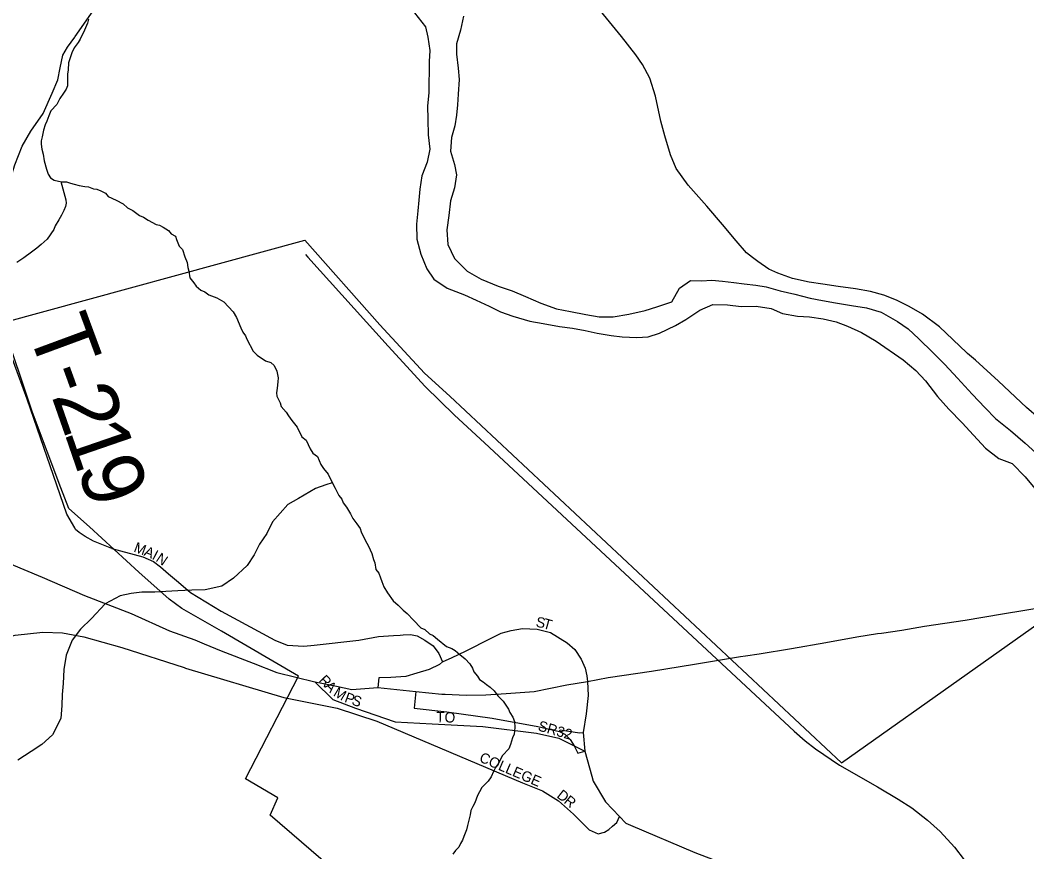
# Model space of a CAD drawing. Extents: x 1310247 to 1664935, y 235267 to 584339.
# Drawn here: x 1486473 to 1491348, y 398512 to 402543 of the extents above; entities that cross this region are included whole.
import ezdxf

# ---------------------------------------------------------------- set-up
doc = ezdxf.new("R2010")
doc.units = 0
for name, color, linetype in [('GM_X_City_Street', 7, 'Continuous'), ('GM_X_City_Street_Text', 7, 'Continuous'), ('GM_X_Corporation', 7, 'Continuous'), ('GM_X_County_Road', 7, 'Continuous'), ('GM_X_Interchange_Ramps', 7, 'Continuous'), ('GM_X_Major_River', 7, 'Continuous'), ('GM_X_Minor_River', 7, 'Continuous'), ('GM_X_Rail_Line', 7, 'Continuous'), ('GM_X_State_Route', 7, 'Continuous'), ('GM_X_Township_Road', 7, 'Continuous'), ('GM_X_Township_Road_Text', 7, 'Continuous'), ('GM_X_Township_ROW', 7, 'Continuous')]:
    doc.layers.add(name, color=color, linetype=linetype)

msp = doc.modelspace()

# ---------------------------------------------------------------- linework, layer by layer
at = {"layer": 'GM_X_City_Street'}
for points in [[(1486916.9, 399981.5), (1487066.1, 399941.7), (1487118.1, 399918.7), (1487153.1, 399893.3), (1487191.8, 399859.6), (1487240.1, 399818.2)], [(1487240.1, 399818.2), (1487298.2, 399768.5), (1487446.8, 399678.9), (1487706.8, 399537.1), (1487765.6, 399512.7), (1487846.5, 399507.8), (1487896, 399513.9), (1488112.3, 399538), (1488207.7, 399555), (1488281.4, 399559.8), (1488313.5, 399562.3)], [(1488313.5, 399562.3), (1488327.3, 399563.4), (1488362.3, 399564.7), (1488395, 399558.6), (1488432.4, 399538), (1488472.3, 399510.3), (1488500.1, 399472.8), (1488518.2, 399432.9), (1488564.1, 399453.4), (1488629.9, 399483.6), (1488753.2, 399547.7), (1488802.7, 399571.9), (1488851, 399585.2), (1488905.4, 399593.6), (1488976.6, 399591.2), (1489040.7, 399575.5), (1489121.6, 399524.8), (1489159.1, 399492.1), (1489189.2, 399446.2), (1489208.6, 399401.5), (1489217, 399364), (1489219.7, 399337.1), (1489223.9, 399270), (1489214.2, 399179.9), (1489199.6, 399090.9), (1489206.7, 399000.3), (1489241, 398878.3)], [(1487266.3, 399404.6), (1487274.1, 399402.1), (1487750.3, 399259.5), (1488007.5, 399207.3), (1488199.7, 399144.9), (1488905.1, 398847), (1489002.5, 398807.5), (1489079.4, 398758.5), (1489152.1, 398694.8), (1489228.5, 398619.2), (1489272.4, 398599.3), (1489301.7, 398607.6), (1489322.7, 398620.3), (1489341.8, 398635.6), (1489361.5, 398653.4), (1489375.4, 398682.7)], [(1487900.2, 399336), (1487987.4, 399249.9), (1488096.5, 399207.6), (1488289.2, 399141.5), (1488467.1, 399131.8), (1488712.9, 399118.7), (1488972.4, 399087.2), (1489082, 399062.9), (1489154.7, 399026.3), (1489206.7, 399000.3)], [(1489241, 398878.3), (1489247.5, 398855.1), (1489307.4, 398753.7), (1489375.4, 398682.7), (1489405.2, 398651.5), (1489428.4, 398641.7), (1489740.3, 398508.4), (1490116.4, 398364.2), (1490359.6, 398271.1), (1490717, 398147.3), (1490944.2, 398061.7), (1491029.9, 398020.8)]]:
    msp.add_lwpolyline(points, dxfattribs=at)
at = {"layer": 'GM_X_Corporation'}
msp.add_lwpolyline([(1488990.7, 397561.9), (1487683.9, 398690.3), (1487720.9, 398773.2), (1487564.1, 398864.9), (1487820, 399362.9), (1487447.5, 399580.5), (1487255.3, 399691.5), (1487194.8, 399735.7), (1487047.4, 399867.2), (1486809, 400086.1), (1486708.2, 400175.8), (1486669.7, 400275.4), (1486532.6, 400641), (1486388, 401075), (1487851.2, 401476.2), (1488214.9, 401066.4), (1488430.7, 400832.3), (1488552.7, 400719.8), (1490450.7, 398943), (1491744.2, 399861)], dxfattribs=at)
at = {"layer": 'GM_X_County_Road'}
msp.add_lwpolyline([(1485407.1, 397346.1), (1485431.1, 397452.2), (1485750.6, 398747.9), (1485799, 398922.1), (1485849.4, 399078.7), (1485913, 399202.8), (1485987.5, 399299), (1486071, 399378), (1486205.4, 399468.8), (1486324.3, 399527.5), (1486448.4, 399561.2), (1486583.4, 399576.5), (1486678.2, 399573.3), (1486780.7, 399553.6), (1486964.7, 399502.7), (1487266.3, 399404.6)], dxfattribs=at)
at = {"layer": 'GM_X_Interchange_Ramps'}
for points in [[(1488518.2, 399432.9), (1488503.1, 399419.2), (1488453.7, 399395.5), (1488393.7, 399377.2), (1488340.4, 399362.2), (1488267.1, 399357.2), (1488209.9, 399355.8), (1488204.4, 399308.4)], [(1488388.4, 399289.2), (1488380, 399208.6), (1488538.6, 399190.6), (1488758.5, 399158.9), (1488980, 399118.9), (1489083.8, 399095.1), (1489109.9, 399082), (1489136.6, 399056.3), (1489154.7, 399026.3), (1489172.2, 398993.3), (1489173.2, 398990.8), (1489206.7, 399000.3)], [(1489083.8, 399095.1), (1489087.4, 399102.4), (1489181.6, 399088.8), (1489199.6, 399090.9)]]:
    msp.add_lwpolyline(points, dxfattribs=at)
at = {"layer": 'GM_X_Major_River'}
for points in [[(1488383.1, 402577.3), (1488436.2, 402510.2), (1488447.4, 402459.8), (1488456.4, 402395.4), (1488453.5, 402341.3), (1488451.1, 402190.8), (1488446, 402126.7), (1488447, 402060.4), (1488447.8, 401986.1), (1488456.7, 401917.8), (1488443.6, 401853.7), (1488418.5, 401787.9), (1488407.4, 401723.9), (1488402.6, 401669.8)], [(1488619.6, 402561.3), (1488604.4, 402493.3), (1488585.3, 402427.4), (1488586.5, 402377.2), (1488593.4, 402308.9), (1488598.5, 402254.6), (1488593.4, 402184.4), (1488590.6, 402132.3), (1488585.7, 402082.2), (1488576.9, 402030.2), (1488561.9, 401974.2), (1488556.8, 401908.1), (1488575.9, 401843.5), (1488585.1, 401793.2), (1488576, 401729.1), (1488557, 401667.2), (1488547.8, 401595.1), (1488538.6, 401527), (1488543.5, 401454.7), (1488576.5, 401387.9), (1488637.7, 401326.7), (1488705.3, 401287.4), (1488787, 401254), (1488854.8, 401230.8), (1488920.5, 401203.6), (1488994.2, 401170.2), (1489070, 401142.9), (1489138, 401129.7), (1489212, 401116.4), (1489276, 401105.3), (1489344.1, 401104.2), (1489420.6, 401117), (1489499.1, 401135.7), (1489555.5, 401152.9), (1489628.1, 401177.8), (1489665.3, 401243.4), (1489718.1, 401280.6), (1489772.2, 401279.7), (1489822.4, 401282.9), (1489874.5, 401278), (1489928.5, 401271.1), (1489978.5, 401264.2), (1490034.6, 401257.3), (1490084.6, 401250.5), (1490152.5, 401231.2), (1490224.4, 401214), (1490298.3, 401194.7), (1490358.3, 401183.7), (1490420.3, 401172.6), (1490498.3, 401159.3), (1490570.4, 401148), (1490642.2, 401126.8), (1490721.7, 401081.3), (1490773.3, 401046.3), (1490824.7, 400997.3), (1490891.8, 400931.9), (1490951, 400872.8), (1491012.1, 400807.5), (1491083.1, 400730.1), (1491146.2, 400662.8), (1491195.5, 400611.8), (1491268.8, 400554.4), (1491340, 400493), (1491391.4, 400446)], [(1488402.6, 401669.8), (1488397.7, 401617.7), (1488392.6, 401553.5), (1488393.5, 401481.3), (1488412.4, 401408.7), (1488441.3, 401338), (1488476.6, 401287.2), (1488540.1, 401244), (1488623.8, 401210.5), (1488681.5, 401185.5), (1488743.3, 401156.3), (1488799, 401129.3), (1488858.8, 401108.3), (1488940.6, 401082.8), (1489004.6, 401071.7), (1489084.6, 401058.3), (1489146.7, 401049.3), (1489208.7, 401038.2), (1489266.6, 401025.2), (1489334.7, 401014), (1489388.7, 401007.1), (1489458.9, 401004), (1489513.1, 401007.1), (1489569.5, 401026.2), (1489646.3, 401063.1), (1489697, 401092.3), (1489763.9, 401137.4), (1489826.5, 401164.4), (1489898.7, 401163.2), (1489964.7, 401154.1), (1490037, 401156.9), (1490109, 401145.7), (1490164.8, 401120.7), (1490236.8, 401107.4), (1490294.9, 401104.5), (1490360.9, 401095.3), (1490424.9, 401080.2), (1490478.7, 401059.2), (1490546.4, 401028), (1490617.9, 400986.7), (1490748.8, 400896.2), (1490810.2, 400845), (1490857.5, 400794), (1490914.4, 400718.8), (1490969.6, 400657.7), (1491034.7, 400590.4), (1491089.9, 400531.3), (1491147.1, 400468.1), (1491212.5, 400418.8), (1491276.2, 400393.7), (1491339.4, 400328.4), (1491394.5, 400263.3)]]:
    msp.add_lwpolyline(points, dxfattribs=at)
at = {"layer": 'GM_X_Minor_River'}
for points in [[(1486803.5, 402547.5), (1486799.2, 402527.4), (1486784.5, 402493.6), (1486763.7, 402449.8), (1486753.4, 402433.8), (1486734.9, 402408.1), (1486722.5, 402384.2), (1486707.6, 402336.3), (1486705, 402302.2), (1486702.6, 402280.1), (1486701.7, 402223.9), (1486695.4, 402208), (1486683, 402188.1), (1486664.5, 402162.3), (1486650, 402134.4), (1486621.4, 402102.8), (1486610.9, 402078.9), (1486602.5, 402052.9), (1486594.1, 402035), (1486585.7, 402009), (1486579.1, 401977), (1486574.7, 401957), (1486574.5, 401941), (1486578.1, 401916.8), (1486583.7, 401892.6), (1486589.2, 401860.4), (1486600.5, 401820), (1486608.2, 401795.8), (1486619.9, 401777.5), (1486637.8, 401767.2), (1486657.8, 401762.8), (1486675.8, 401758.5), (1486697.9, 401758.1), (1486715.8, 401751.8), (1486733.8, 401747.4), (1486757.8, 401741), (1486785.8, 401736.5), (1486803.8, 401734.1), (1486827.8, 401725.7), (1486843.8, 401723.4), (1486863.7, 401715), (1486885.7, 401704.6), (1486899.4, 401688.3), (1486937.2, 401669.6), (1486971.1, 401652.9), (1486992.8, 401632.4), (1487018.7, 401619.9), (1487050.4, 401595.3), (1487070.3, 401586.9), (1487092.2, 401572.5), (1487132, 401551.7), (1487148, 401549.4), (1487165.9, 401539), (1487191.7, 401522.5), (1487203.5, 401506.2), (1487225.4, 401495.8), (1487229.1, 401479.7), (1487242.6, 401447.3), (1487258.4, 401431), (1487269.8, 401394.6), (1487281.4, 401368.3), (1487285, 401344.2), (1487288.8, 401326), (1487294.2, 401293.8), (1487313.9, 401269.4), (1487325.7, 401253.1), (1487347.4, 401234.6), (1487367.4, 401226.3), (1487387.2, 401211.9), (1487425.1, 401197.1), (1487458.9, 401176.5), (1487504.2, 401129.5), (1487519.8, 401101.1), (1487541.1, 401050.5), (1487550.8, 401030.3), (1487564.5, 401012), (1487570.2, 400995.8), (1487601.4, 400939), (1487621.1, 400918.6), (1487660.8, 400891.8), (1487686.8, 400883.3), (1487702.6, 400869), (1487716.2, 400840.6), (1487721.6, 400808.4), (1487721.3, 400790.3), (1487716.8, 400758.3), (1487714.4, 400736.2), (1487716.1, 400720.1)], [(1486669.2, 401760.1), (1486694.4, 401671.8), (1486696.1, 401655.7), (1486691.8, 401639.7), (1486683.5, 401619.8), (1486673.1, 401597.9), (1486660.6, 401574), (1486642.1, 401546.2), (1486635.8, 401528.2), (1486602.9, 401480.6), (1486574.3, 401455), (1486553.9, 401437.3), (1486527.5, 401417.7), (1486490.9, 401390.2), (1486456.4, 401368.7)], [(1487716.1, 400720.1), (1487731.7, 400687.8), (1487737.4, 400669.6), (1487761, 400643.1), (1487772.7, 400624.8), (1487788.4, 400602.4), (1487814, 400569.8), (1487837.3, 400523.3), (1487857.1, 400506.8), (1487876.4, 400464.3), (1487890.1, 400444), (1487911.9, 400427.6), (1487929.4, 400389.1), (1487941.1, 400368.8), (1487964.7, 400342.3), (1487978.2, 400312), (1487997.7, 400273.5), (1488015.2, 400239), (1488030.9, 400220.7), (1488036.6, 400202.5), (1488052.3, 400182.1), (1488071.9, 400149.7), (1488083.5, 400127.4), (1488103.2, 400100.9), (1488118.8, 400078.6), (1488124.6, 400062.4), (1488144, 400021.9), (1488159.6, 399993.5), (1488167.3, 399975.3), (1488175, 399957.1), (1488184.6, 399928.8), (1488190.3, 399912.7), (1488195.8, 399880.4), (1488209.5, 399862.1), (1488217.2, 399839.9), (1488224.9, 399821.7), (1488234.5, 399795.4), (1488252.1, 399767), (1488279.5, 399728.4), (1488303.3, 399707.9), (1488327, 399683.4), (1488346.8, 399667), (1488378.3, 399634.3), (1488413.8, 399597.5), (1488431.8, 399589.2), (1488455.5, 399568.7), (1488473.4, 399560.3), (1488493.2, 399541.9), (1488536.8, 399507), (1488562.7, 399496.5), (1488578.6, 399488.2), (1488602.4, 399467.7), (1488628.1, 399447.2), (1488649.8, 399422.7), (1488663.5, 399402.4), (1488669.2, 399384.2), (1488686.9, 399363.8), (1488696.7, 399347.6), (1488714.5, 399335.2), (1488730.4, 399322.9), (1488748.2, 399310.5), (1488768, 399292.1), (1488785.7, 399267.7), (1488811.3, 399241.2), (1488825.1, 399222.9), (1488836.8, 399202.6), (1488844.5, 399186.4), (1488858.2, 399164), (1488865.9, 399143.8), (1488867.4, 399113.7), (1488864.8, 399081.6), (1488856.5, 399063.7), (1488847.9, 399031.7), (1488839.6, 399011.8), (1488808.9, 398978.2), (1488788.2, 398938.4), (1488773.8, 398920.6), (1488765.4, 398900.6), (1488753, 398874.7), (1488738.6, 398854.9), (1488724.3, 398839.1), (1488707.9, 398823.3), (1488697.6, 398803.4), (1488687.2, 398785.5), (1488674.6, 398749.6), (1488664.2, 398731.7), (1488655.9, 398711.8), (1488651.5, 398691.8), (1488638.6, 398639.8), (1488634.2, 398617.8), (1488621.6, 398585.9), (1488615.3, 398568), (1488605, 398552.1), (1488596.7, 398534.1), (1488580.3, 398518.4), (1488568, 398500.5)], [(1487984.1, 400300.3), (1487953.6, 400290.5), (1487903.1, 400273.3), (1487819.9, 400224.6), (1487769.2, 400195.4), (1487695.5, 400110.4), (1487666.5, 400054.7), (1487631.4, 400003.1), (1487606.5, 399951.4), (1487571.5, 399899.8), (1487506.2, 399838.7), (1487449.3, 399799.6), (1487368.7, 399780.9), (1487304.4, 399780), (1487236.1, 399777.2), (1487177.8, 399774.1), (1487125.6, 399771), (1487061.3, 399770.1), (1487011, 399763), (1486956.6, 399751.9), (1486883.7, 399713), (1486818.2, 399641.9), (1486765.2, 399590.6), (1486724.1, 399537.2), (1486694.8, 399465.4), (1486683.5, 399395.4), (1486680.4, 399327.2), (1486675.5, 399275.1), (1486674.5, 399221), (1486669.5, 399158.8), (1486630, 399079.3), (1486577, 399032), (1486526.2, 398998.8), (1486461.2, 398955.8)]]:
    msp.add_lwpolyline(points, dxfattribs=at)
at = {"layer": 'GM_X_Rail_Line'}
for points in [[(1487855, 401406.9), (1487866.5, 401394)], [(1487866.5, 401394), (1488254.5, 400961.7), (1488433.2, 400766.5), (1488575.6, 400627.9), (1488721.8, 400493.2), (1490220.9, 399095.9), (1490273.7, 399049.1), (1490323.7, 399011.2), (1490440.9, 398932.6), (1490624, 398827.5), (1490724.1, 398767.6), (1490791.1, 398724.7), (1490867, 398665.3), (1490928.6, 398609.8), (1490997.4, 398534.4), (1491044.6, 398473.4)]]:
    msp.add_lwpolyline(points, dxfattribs=at)
at = {"layer": 'GM_X_State_Route'}
for points in [[(1490018.5, 401392.7), (1489990.2, 401414.4), (1489940.5, 401473.4), (1489874.3, 401551.6), (1489798.2, 401640.5), (1489707.9, 401742.9), (1489649.6, 401823.9), (1489621.9, 401890), (1489594.2, 401981.8), (1489575.2, 402053.1), (1489550.1, 402174.5), (1489522.3, 402260.5), (1489486.8, 402326.7), (1489454.1, 402375), (1489384.4, 402463.2), (1489269.2, 402604.7)], [(1491060.7, 400926.9), (1491055.4, 400931.5), (1490925.3, 401056), (1490842.8, 401117.1), (1490778.1, 401154.8), (1490716.2, 401186.1), (1490655.1, 401208.9), (1490591.1, 401227.3), (1490518.5, 401240.1), (1490434.6, 401251.5), (1490360, 401263.6), (1490293.1, 401272.1), (1490212.1, 401289.9), (1490141.7, 401316.9), (1490098.3, 401335.4), (1490045, 401372.4), (1490018.5, 401392.7)], [(1492028.1, 399941), (1491942.4, 400031.2), (1491804.1, 400191.3), (1491701.7, 400317.2), (1491595.1, 400438.1), (1491466.1, 400561.4), (1491345.2, 400665.7), (1491209.7, 400792.9), (1491098.8, 400893.9), (1491060.7, 400926.9)], [(1484749.1, 400610.1), (1484986, 400514.8), (1485272.8, 400383), (1485577.1, 400257.9), (1485817.6, 400156.3), (1486095.7, 400043.2), (1486350.4, 399938.7), (1486579.6, 399843.3), (1486784.6, 399754.1), (1487009.9, 399666.3), (1487195.8, 399583.5), (1487318, 399539), (1487363.2, 399520)], [(1490644.2, 399572.2), (1490742.5, 399586.1), (1490851.7, 399606), (1491049.4, 399634.1), (1491229.8, 399664.7), (1491435.8, 399699.4), (1491624.5, 399732.5), (1491828, 399764), (1492010.8, 399792.1), (1492127.2, 399811.3)], [(1489985.7, 399462.2), (1490051.7, 399471.9), (1490207.2, 399496.7), (1490374.3, 399525.7), (1490524.1, 399553), (1490625, 399569.5), (1490644.2, 399572.2)], [(1487363.2, 399520), (1487445.4, 399485.5), (1487600.7, 399425.6), (1487715.3, 399381.1), (1487900.2, 399336), (1487934, 399329.3)], [(1488388.4, 399289.2), (1488514.8, 399276), (1488531, 399275.4), (1488633.1, 399271.4), (1488727.5, 399273.3), (1488825.9, 399279.2), (1488962.5, 399288.3), (1489120.1, 399320.5), (1489219.7, 399337.1), (1489319.5, 399356.1), (1489530.5, 399386.7), (1489738.9, 399421.4), (1489961.5, 399458.7), (1489985.7, 399462.2)], [(1487934, 399329.3), (1488004.6, 399315.4), (1488078.1, 399298.3), (1488204.4, 399308.4), (1488388.4, 399289.2)]]:
    msp.add_lwpolyline(points, dxfattribs=at)
at = {"layer": 'GM_X_Township_Road'}
for points in [[(1486312.8, 401359.8), (1486334.9, 401404.8), (1486386.2, 401505.5), (1486404.3, 401590.1), (1486406.3, 401652.5), (1486416.4, 401741.1), (1486446.6, 401840.8), (1486482.9, 401932.4), (1486524.1, 402004.9), (1486583.5, 402090.4), (1486627.8, 402188.1), (1486654.7, 402252.5), (1486667.1, 402310.9), (1486679.2, 402373.3), (1486702.3, 402411.6), (1486737.6, 402459.9), (1486739.6, 402462.8)], [(1486737, 400081.9), (1486698.1, 400148.8), (1486507, 400705.2), (1486372.1, 401067.6), (1486347.9, 401162.2), (1486301.7, 401308.2), (1486308.7, 401351.5), (1486312.8, 401359.8)], [(1486916.9, 399981.5), (1486827.9, 400017.8), (1486787.1, 400039.4), (1486758.2, 400059.9), (1486741.4, 400074.3), (1486737, 400081.9)]]:
    msp.add_lwpolyline(points, dxfattribs=at)
at = {"layer": 'GM_X_Township_ROW'}
msp.add_lwpolyline([(1486739.6, 402462.8), (1486891.7, 402681.5), (1486936.9, 402717.7), (1486992.3, 402722.7), (1487123.1, 402725.7), (1487181.5, 402716.6), (1487322.4, 402684.7), (1487407.1, 402679.4), (1487472.5, 402661.3), (1487513.8, 402653.2), (1487567.1, 402652.2), (1487612.4, 402661.3), (1487658.7, 402671.3), (1487731.2, 402685.4), (1488061.4, 402667.4)], dxfattribs=at)

# ---------------------------------------------------------------- texts
at = {"layer": 'GM_X_City_Street_Text'}
for s, rotation, p in [('M', 339.6123, (1487019.3, 399967.5)), ('A', 337.2003, (1487068.3, 399949.3)), ('I', 332.2618, (1487107.9, 399932.7)), ('N', 325.9462, (1487126.1, 399923.2)), ('S', 348.8937, (1488967.3, 399603.1)), ('T', 344.5388, (1489000.8, 399596.5)), ('R', 313.7804, (1487916.3, 399340.2)), ('A', 313.7889, (1487943.7, 399311.6)), ('M', 329.2246, (1487985.6, 399270.7)), ('P', 339.6157, (1488039.9, 399239.5)), ('S', 341.3974, (1488074.5, 399226.6)), ('TO', 358.0261, (1488486.1, 399140.8)), ('SR32', 343.8089, (1488976.8, 399100.9)), ('COLLEGE', 336.6805, (1488691.9, 398950.9)), ('D', 321.8317, (1489067.6, 398778.3)), ('R', 320.8131, (1489102, 398751.3))]:
    msp.add_text(s, height=50, rotation=rotation, dxfattribs=at).set_placement(p)
at = {"layer": 'GM_X_Township_Road_Text'}
for s, rotation, p in [('T', 290.3051, (1486504.9, 401044.8)), ('-', 289.8314, (1486582.4, 400835.4)), ('2', 289.2597, (1486623.5, 400721.3)), ('1', 289.0079, (1486683.9, 400548.5)), ('9', 289.818, (1486745.2, 400370.8))]:
    msp.add_text(s, height=300, rotation=rotation, dxfattribs=at).set_placement(p)

doc.saveas('drawing.dxf')
